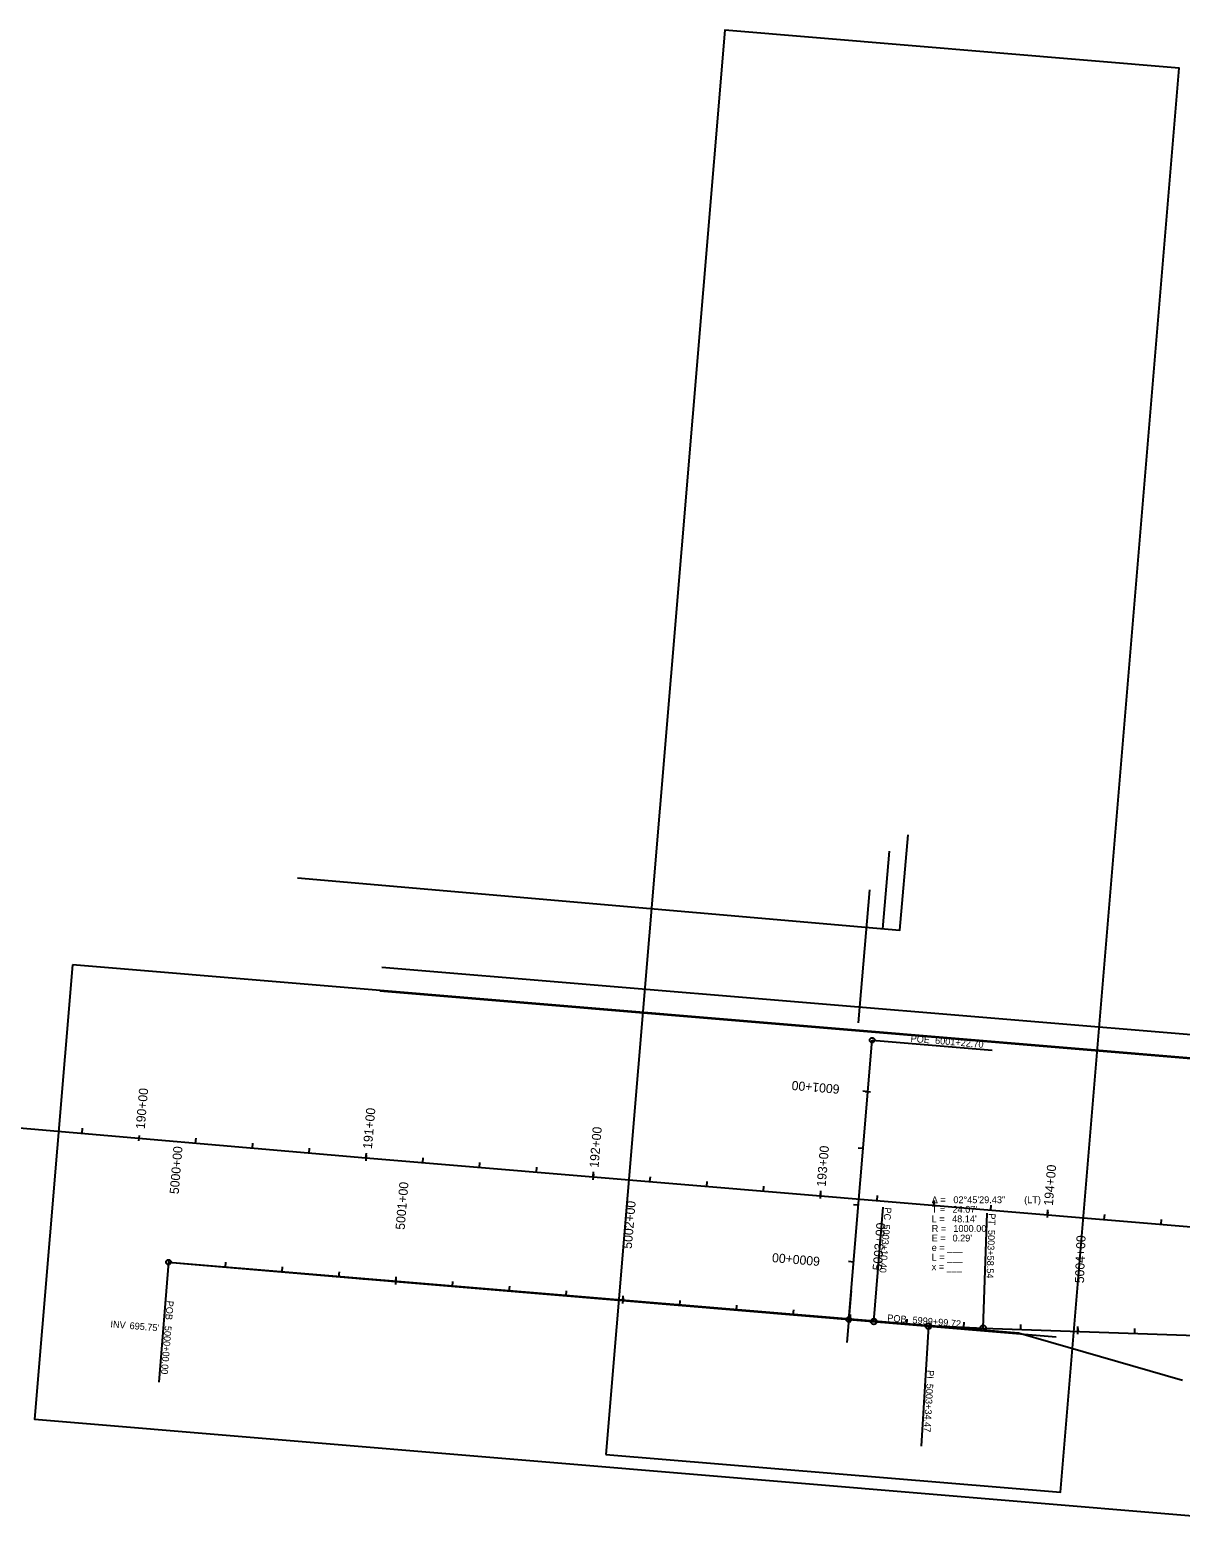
# Model space of a CAD drawing. Extents: x 20500393 to 20505339, y 7953466 to 7954298.
# Drawn here: x 20502657 to 20503162, y 7953636 to 7954298 of the extents above; entities that cross this region are included whole.
import ezdxf

# ---------------------------------------------------------------- set-up
doc = ezdxf.new("R2010")
doc.units = 0
for name, color, linetype in [('_CIVIL_CONSTRUCTION', 7, 'Continuous'), ('Alignment', 7, 'Continuous'), ('Draft_2', 7, 'Continuous'), ('Draft_3', 7, 'Continuous'), ('Draft_7', 7, 'Continuous'), ('NamedBoundary', 7, 'Continuous'), ('TextAlignment', 7, 'Continuous'), ('TextAlignmentLrg', 7, 'Continuous'), ('TextAlignmentSml', 7, 'Continuous')]:
    doc.layers.add(name, color=color, linetype=linetype)

msp = doc.modelspace()

# ---------------------------------------------------------------- linework, layer by layer
at = {"layer": '_CIVIL_CONSTRUCTION'}
for p, q in [((20502202.58, 7953855.42), (20502804.53, 7953803.04)), ((20502202.58, 7953855.42), (20502804.53, 7953803.04)), ((20502804.53, 7953803.04), (20504247.96, 7953682.58)), ((20502804.53, 7953803.04), (20504247.96, 7953682.58)), ((20502717.94, 7953757.32), (20502727.91, 7953756.51)), ((20502727.91, 7953756.51), (20502800.03, 7953750.23)), ((20502800.03, 7953750.23), (20503027.24, 7953731.27)), ((20503075.29, 7953728.42), (20503255.62, 7953722.08))]:
    msp.add_line(p, q, dxfattribs=at)
msp.add_arc((20503110.4, 7954727.8), 1000, 265.22957, 267.98774, dxfattribs=at)
at = {"layer": 'Alignment'}
for p, q in [((20503016.32, 7953732.18), (20503026.54, 7953854.74)), ((20502717.94, 7953757.32), (20502727.91, 7953756.51)), ((20502717.94, 7953757.32), (20502727.91, 7953756.51)), ((20502727.91, 7953756.51), (20502800.03, 7953750.23)), ((20502727.91, 7953756.51), (20502800.03, 7953750.23)), ((20502800.03, 7953750.23), (20503027.24, 7953731.27)), ((20502800.03, 7953750.23), (20503027.24, 7953731.27)), ((20503075.29, 7953728.42), (20503255.62, 7953722.08)), ((20503075.29, 7953728.42), (20503255.62, 7953722.08))]:
    msp.add_line(p, q, dxfattribs=at)
msp.add_arc((20503110.4, 7954727.8), 1000, 265.22957, 267.98774, dxfattribs=at)
msp.add_arc((20503110.4, 7954727.8), 1000, 265.22957, 267.98774, dxfattribs=at)
at = {"layer": 'Draft_2'}
for p, q in [((20503031.23, 7953903.59), (20503034.19, 7953937.6)), ((20503025.46, 7953920.68), (20503020.38, 7953862.26)), ((20502811.52, 7953886.75), (20504254.94, 7953766.29)), ((20502810.65, 7953876.37), (20504254.08, 7953755.91))]:
    msp.add_line(p, q, dxfattribs=at)
msp.add_lwpolyline([(20502774.54, 7953925.92), (20503038.7, 7953902.94), (20503042.34, 7953944.76)], dxfattribs=at)
at = {"layer": 'Draft_3'}
for p, q in [((20502727.91, 7953756.51), (20502800.03, 7953750.23)), ((20502727.91, 7953756.51), (20502800.03, 7953750.23)), ((20502727.91, 7953756.51), (20502800.03, 7953750.23)), ((20502800.03, 7953750.23), (20503107.28, 7953724.59)), ((20502800.03, 7953750.23), (20503027.24, 7953731.27)), ((20502800.03, 7953750.23), (20502804.65, 7953749.84)), ((20503017.4, 7953744.69), (20503015.52, 7953722.13))]:
    msp.add_line(p, q, dxfattribs=at)
msp.add_arc((20503110.4, 7954727.8), 1000, 265.22957, 267.98774, dxfattribs=at)
at = {"layer": 'Draft_7'}
for p, q in [((20502717.91, 7953757.33), (20503090.75, 7953726.26)), ((20503090.75, 7953726.26), (20503162.66, 7953705.61))]:
    msp.add_line(p, q, dxfattribs=at)
at = {"layer": 'NamedBoundary'}
for points in [[(20502909.81, 7953672.99), (20503109.12, 7953656.36), (20503161.27, 7954281.18), (20502961.96, 7954297.82)], [(20502675.82, 7953887.73), (20502659.18, 7953688.42), (20503282.86, 7953636.38), (20503299.49, 7953835.68)]]:
    msp.add_lwpolyline(points, close=True, dxfattribs=at)
at = {"layer": 'TextAlignment'}
for p, q in [((20503026.54, 7953854.74), (20503079.16, 7953850.35)), ((20503079.16, 7953850.35), (20503079.16, 7953850.35)), ((20503027.24, 7953731.27), (20503031.43, 7953781.49)), ((20503031.43, 7953781.49), (20503031.43, 7953781.49)), ((20503075.29, 7953728.42), (20503077.06, 7953778.79)), ((20503077.06, 7953778.79), (20503077.06, 7953778.79)), ((20502717.94, 7953757.32), (20502713.63, 7953704.7)), ((20503016.32, 7953732.18), (20503068.93, 7953727.79)), ((20503051.23, 7953729.27), (20503048.11, 7953676.56)), ((20503068.93, 7953727.79), (20503068.93, 7953727.79)), ((20502713.63, 7953704.7), (20502713.63, 7953704.7)), ((20503048.11, 7953676.56), (20503048.11, 7953676.56))]:
    msp.add_line(p, q, dxfattribs=at)
for centre, radius in [((20503026.54, 7953854.74), 1.07), ((20502717.94, 7953757.32), 1.07), ((20503016.32, 7953732.18), 1.07), ((20503027.24, 7953731.27), 1.25), ((20503051.23, 7953729.27), 1.25), ((20503075.29, 7953728.42), 1.25)]:
    msp.add_circle(centre, radius, dxfattribs=at)
at = {"layer": 'TextAlignmentLrg'}
for p, q in [((20503024.66, 7953832.11), (20503022.48, 7953832.29)), ((20502705.01, 7953812.93), (20502704.8, 7953810.49)), ((20502804.53, 7953803.04), (20502804.72, 7953805.21)), ((20502904.18, 7953794.72), (20502904.37, 7953796.9)), ((20503003.84, 7953786.4), (20503004.02, 7953788.58)), ((20503103.49, 7953778.09), (20503103.67, 7953780.26)), ((20502718.04, 7953758.54), (20502717.84, 7953756.1)), ((20502817.57, 7953748.76), (20502817.75, 7953750.94)), ((20502917.22, 7953740.45), (20502917.41, 7953742.62)), ((20503016.88, 7953732.13), (20503017.06, 7953734.31)), ((20503015.12, 7953732.56), (20503017.56, 7953732.36)), ((20503116.73, 7953726.96), (20503116.8, 7953729.15))]:
    msp.add_line(p, q, dxfattribs=at)
at = {"layer": 'TextAlignmentSml'}
for p, q in [((20503023.44, 7953832.21), (20503025.88, 7953832.01)), ((20502680, 7953813.87), (20502680.19, 7953816.05)), ((20502705.01, 7953812.93), (20502704.8, 7953810.49)), ((20502729.81, 7953809.54), (20502730, 7953811.72)), ((20502754.72, 7953807.37), (20502754.91, 7953809.55)), ((20502779.62, 7953805.2), (20502779.81, 7953807.38)), ((20503022.58, 7953807.2), (20503020.4, 7953807.38)), ((20502804.64, 7953804.26), (20502804.42, 7953801.82)), ((20502829.44, 7953800.96), (20502829.63, 7953803.13)), ((20502854.36, 7953798.88), (20502854.54, 7953801.06)), ((20502879.27, 7953796.8), (20502879.45, 7953798.98)), ((20502904.29, 7953795.94), (20502904.08, 7953793.5)), ((20502929.1, 7953792.64), (20502929.28, 7953794.82)), ((20502954.01, 7953790.56), (20502954.19, 7953792.74)), ((20502978.92, 7953788.48), (20502979.11, 7953790.66)), ((20503003.94, 7953787.62), (20503003.74, 7953785.18)), ((20503020.5, 7953782.28), (20503018.32, 7953782.47)), ((20503028.75, 7953784.33), (20503028.93, 7953786.5)), ((20503053.66, 7953782.25), (20503053.85, 7953784.42)), ((20503078.58, 7953780.17), (20503078.76, 7953782.34)), ((20503103.59, 7953779.31), (20503103.39, 7953776.87)), ((20503128.4, 7953776.01), (20503128.59, 7953778.19)), ((20503153.32, 7953773.93), (20503153.5, 7953776.11)), ((20502718.04, 7953758.54), (20502717.84, 7953756.1)), ((20502742.85, 7953755.2), (20502743.04, 7953757.38)), ((20502767.75, 7953753.04), (20502767.94, 7953755.21)), ((20503018.42, 7953757.37), (20503016.24, 7953757.55)), ((20502792.66, 7953750.87), (20502792.85, 7953753.05)), ((20502817.67, 7953749.98), (20502817.47, 7953747.55)), ((20502842.48, 7953746.69), (20502842.67, 7953748.86)), ((20502867.4, 7953744.61), (20502867.58, 7953746.78)), ((20502892.31, 7953742.53), (20502892.49, 7953744.7)), ((20502917.33, 7953741.67), (20502917.12, 7953739.23)), ((20502942.14, 7953738.37), (20502942.32, 7953740.55)), ((20502967.05, 7953736.29), (20502967.23, 7953738.47)), ((20502991.96, 7953734.21), (20502992.15, 7953736.39)), ((20503015.12, 7953732.56), (20503017.56, 7953732.36)), ((20503016.98, 7953733.35), (20503016.78, 7953730.91)), ((20503041.8, 7953730.16), (20503041.95, 7953732.34)), ((20503066.76, 7953728.76), (20503066.85, 7953730.94)), ((20503091.74, 7953727.84), (20503091.82, 7953730.02)), ((20503116.77, 7953728.19), (20503116.68, 7953725.74)), ((20503141.71, 7953726.09), (20503141.79, 7953728.27))]:
    msp.add_line(p, q, dxfattribs=at)

# ---------------------------------------------------------------- texts
at = {"layer": 'Draft_2'}
for s, p in [('INV ', (20502692.35, 7953728.74)), ("695.75'", (20502700.74, 7953728.04))]:
    msp.add_text(s, height=3, rotation=355.22957, dxfattribs=at).set_placement(p)
at = {"layer": 'TextAlignment'}
for s, rotation, p in [('POE ', 355.22957, (20503043.34, 7953854)), ('6001+22.70', 355.22957, (20503054.06, 7953853.1)), ('PC', 265.22957, (20503032.09, 7953781.44)), ('5003+10.40', 265.22957, (20503031.47, 7953773.99)), ('PT', 267.98774, (20503077.72, 7953778.77)), ('5003+58.54', 267.98774, (20503077.46, 7953771.51)), ('POB ', 265.31578, (20502717.22, 7953740.52)), ('POB ', 355.22957, (20503033.11, 7953731.44)), ('5000+00.00', 265.31578, (20502716.32, 7953729.48)), ('5999+99.72', 355.22957, (20503044.16, 7953730.52)), ('PI ', 266.60865, (20503050.75, 7953710.04)), ('5003+34.47', 266.60865, (20503050.4, 7953704.07))]:
    msp.add_text(s, height=3, rotation=rotation, dxfattribs=at).set_placement(p)
for s, p in [('T = ', (20503052.68, 7953779)), ('Δ = ', (20503052.68, 7953783.2)), ("24.07'", (20503061.81, 7953779)), ('02°45\'29.43"', (20503062.18, 7953783.2)), (' (LT)', (20503092.12, 7953783.2)), ('L = ', (20503052.68, 7953774.8)), ("48.14'", (20503061.62, 7953774.8)), ('R = ', (20503052.68, 7953770.6)), ('E = ', (20503052.68, 7953766.4)), ("0.29'", (20503061.81, 7953766.4)), ("1000.00'", (20503062.17, 7953770.6)), ('e = ___ ', (20503052.68, 7953762.2)), ('L = ___', (20503052.68, 7953758)), ('x = ___', (20503052.68, 7953753.8))]:
    msp.add_text(s, height=3, dxfattribs=at).set_placement(p)
at = {"layer": 'TextAlignmentLrg'}
for s, rotation, p in [('190+00', 85.02642, (20502707.48, 7953815.55)), ('5000+00', 85.31578, (20502722.38, 7953787.06))]:
    msp.add_text(s, height=4.008, rotation=rotation, dxfattribs=at).set_placement(p)
at = {"layer": 'TextAlignmentSml'}
for s, rotation, p in [('6001+00', 175.22957, (20503012.4, 7953835.14)), ('191+00', 85.02642, (20502807.13, 7953806.88)), ('192+00', 85.22957, (20502906.52, 7953798.59)), ('193+00', 85.22957, (20503006.17, 7953790.28)), ('194+00', 85.22957, (20503105.83, 7953781.96)), ('5001+00', 85.22957, (20502821.47, 7953771.41)), ('5002+00', 85.22957, (20502921.12, 7953763.09)), ('5003+00', 85.22957, (20503030.71, 7953753.53)), ('5004+00', 87.98774, (20503119.47, 7953748.03)), ('6000+00', 175.22957, (20503003.8, 7953759.61))]:
    msp.add_text(s, height=4.008, rotation=rotation, dxfattribs=at).set_placement(p)

doc.saveas('drawing.dxf')
